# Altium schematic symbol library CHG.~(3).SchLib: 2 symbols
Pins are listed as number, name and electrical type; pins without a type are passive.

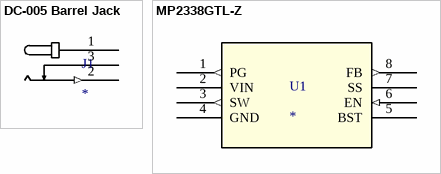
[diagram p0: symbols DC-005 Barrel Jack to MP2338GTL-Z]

## DC-005 Barrel Jack
designator J1
Barrel Jack to simplify PCB complexity
pins: 1 VIN (power), 2 SW (out), 3 GND (power)

## MP2338GTL-Z
designator U1
MP2338 IC
pins: 1 PG (out), 2 VIN (power), 3 SW (out), 4 GND (power), 5 BST (power), 6 EN (in), 7 SS, 8 FB (out)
